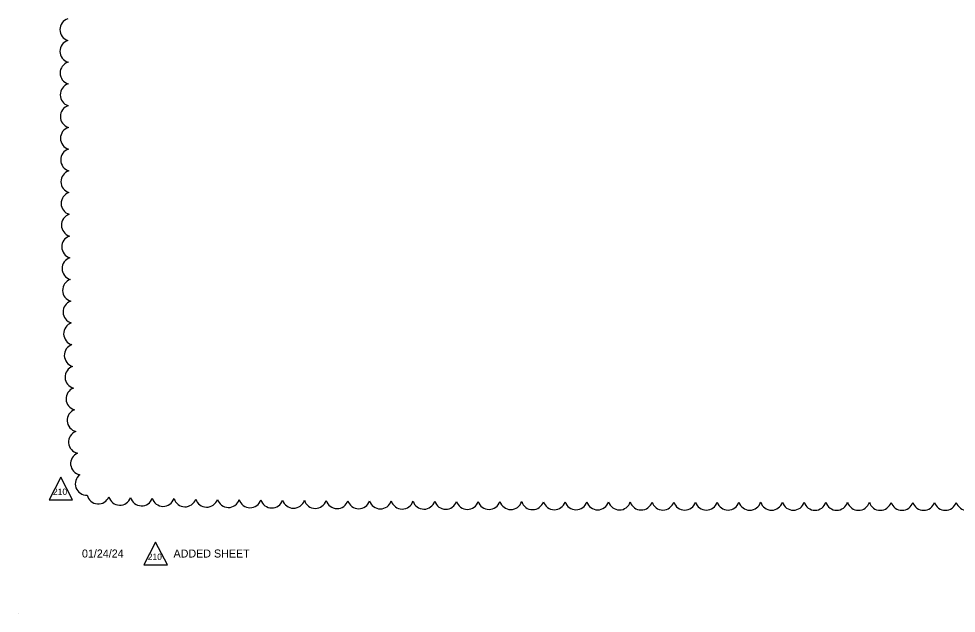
# Model space of a CAD drawing. Extents: x -811 to 10319, y -2309 to 9962.
# Drawn here: x -811.34 to -803.18, y -2284.27 to -2279.1 of the extents above; entities that cross this region are included whole.
import ezdxf

# ---------------------------------------------------------------- set-up
doc = ezdxf.new("R2010")
doc.units = 0
doc.layers.add('ScratchEle_dp', color=7, linetype='Continuous')
doc.layers.add('SheetBorder_dp', color=7, linetype='Continuous')

msp = doc.modelspace()

# ---------------------------------------------------------------- linework, layer by layer
at = {"layer": 'ScratchEle_dp'}
for points in [[(-810.9694, -2283.0907), (-811.0715, -2283.2874), (-810.8673, -2283.2874)], [(-810.1449, -2283.6566), (-810.247, -2283.8533), (-810.0428, -2283.8533)]]:
    msp.add_lwpolyline(points, close=True, dxfattribs=at)
for centre, start, end in [((-810.8785, -2279.198), 107.65843, 252.65843), ((-810.8779, -2279.387), 107.709, 252.709), ((-810.8771, -2279.5759), 107.76343, 252.76343), ((-810.8761, -2279.7649), 107.82224, 252.82224), ((-810.8749, -2279.9539), 107.88605, 252.88605), ((-810.8736, -2280.1428), 107.95561, 252.95561), ((-810.8719, -2280.3318), 108.03183, 253.03183), ((-810.87, -2280.5207), 108.11586, 253.11586), ((-810.8679, -2280.7097), 108.20912, 253.20912), ((-810.8653, -2280.8986), 108.31345, 253.31345), ((-810.8625, -2281.0875), 108.43121, 253.43121), ((-810.8592, -2281.2764), 108.56556, 253.56556), ((-810.8554, -2281.4653), 108.72081, 253.72081), ((-810.8511, -2281.6541), 108.903, 253.903), ((-810.8461, -2281.843), 109.12096, 254.12096), ((-810.8403, -2282.0317), 109.38818, 254.38818), ((-810.8335, -2282.2204), 109.72657, 254.72657), ((-810.8255, -2282.409), 110.17469, 255.17469), ((-810.8156, -2282.5974), 110.80877, 255.80877), ((-810.8031, -2282.7855), 111.80931, 256.80931), ((-810.7858, -2282.9726), 113.77584, 258.77584), ((-810.7447, -2283.1485), 127.48462, 272.48462), ((-810.644, -2283.2249), 193.17348, 338.17348), ((-810.4565, -2283.2354), 195.39639, 340.39639), ((-810.2679, -2283.2414), 195.97806, 340.97806), ((-810.0791, -2283.2459), 196.28744, 341.28744), ((-809.8902, -2283.2496), 196.48754, 341.48754), ((-809.7013, -2283.2527), 196.63065, 341.63065), ((-809.5124, -2283.2554), 196.73959, 341.73959), ((-809.3235, -2283.2577), 196.8261, 341.8261), ((-809.1345, -2283.2598), 196.89697, 341.89697), ((-808.9455, -2283.2617), 196.95641, 341.95641), ((-808.7566, -2283.2634), 197.0072, 342.0072), ((-808.5676, -2283.265), 197.05125, 342.05125), ((-808.3786, -2283.2664), 197.08993, 342.08993), ((-808.1897, -2283.2677), 197.12425, 342.12425), ((-808.0007, -2283.2689), 197.15498, 342.15498), ((-807.8117, -2283.27), 197.18269, 342.18269), ((-807.6227, -2283.271), 197.20786, 342.20786), ((-807.4337, -2283.2719), 197.23085, 342.23085), ((-807.2447, -2283.2728), 197.25195, 342.25195), ((-807.0557, -2283.2735), 197.27142, 342.27142), ((-806.8667, -2283.2743), 197.28945, 342.28945), ((-806.6778, -2283.2749), 197.30621, 342.30621), ((-806.4888, -2283.2756), 197.32184, 342.32184), ((-806.2998, -2283.2761), 197.33647, 342.33647), ((-806.1108, -2283.2766), 197.3502, 342.3502), ((-805.9218, -2283.2771), 197.36311, 342.36311), ((-805.7328, -2283.2775), 197.37529, 342.37529), ((-805.5438, -2283.2779), 197.3868, 342.3868), ((-805.3548, -2283.2783), 197.3977, 342.3977), ((-805.1658, -2283.2786), 197.40804, 342.40804), ((-804.9768, -2283.2789), 197.41787, 342.41787), ((-804.7878, -2283.2791), 197.42723, 342.42723), ((-804.5988, -2283.2794), 197.43616, 342.43616), ((-804.4098, -2283.2796), 197.44468, 342.44468), ((-804.2208, -2283.2797), 197.45283, 342.45283), ((-804.0318, -2283.2799), 197.46064, 342.46064), ((-803.8428, -2283.28), 197.46812, 342.46812), ((-803.6538, -2283.2801), 197.4753, 342.4753), ((-803.4648, -2283.2802), 197.4822, 342.4822), ((-803.2759, -2283.2802), 197.48884, 342.48884), ((-803.0869, -2283.2802), 197.49523, 342.49523)]:
    msp.add_arc(centre, 0.0991, start, end, dxfattribs=at)
at = {"layer": 'SheetBorder_dp'}
msp.add_line((-811.3358, -2284.2746), (-811.3358, -2284.2746), dxfattribs=at)

# ---------------------------------------------------------------- texts
at = {"layer": 'ScratchEle_dp'}
for s, height, p in [('210', 0.0551, (-811.038, -2283.2452)), ('01/24/24', 0.0696, (-810.7859, -2283.7898)), ('ADDED SHEET', 0.0696, (-809.9894, -2283.7898)), ('210', 0.0551, (-810.2135, -2283.8111))]:
    msp.add_text(s, height=height, dxfattribs=at).set_placement(p)

doc.saveas('drawing.dxf')
